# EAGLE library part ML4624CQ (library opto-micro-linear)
FIBER OPTIC DATA QUANTIZER
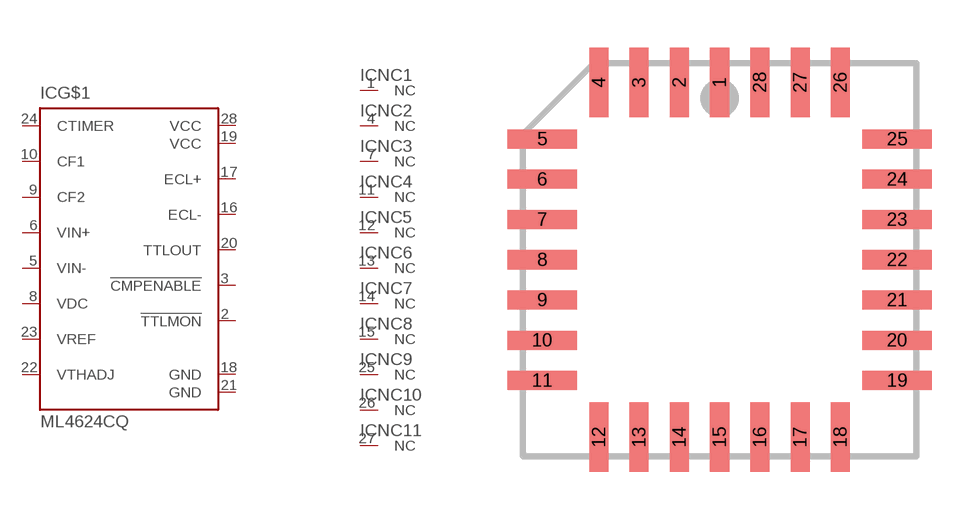
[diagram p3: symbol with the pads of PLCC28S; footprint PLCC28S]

Designator prefix IC; gates G$1=ML4624 NC1=NC NC2=NC NC3=NC NC4=NC NC5=NC NC6=NC NC7=NC NC8=NC NC9=NC NC10=NC NC11=NC

## ML4624CQ (OC_FARNELL: unknown; OC_NEWARK: unknown)  [PLCC28S]
1  NC1:NC  nc
2  G$1:!TTLMON  out
3  G$1:!CMPENABLE  in
4  NC2:NC  nc
5  G$1:VIN-  in
6  G$1:VIN+  in
7  NC3:NC  nc
8  G$1:VDC  pas
9  G$1:CF2  pas
10  G$1:CF1  pas
11  NC4:NC  nc
12  NC5:NC  nc
13  NC6:NC  nc
14  NC7:NC  nc
15  NC8:NC  nc
16  G$1:ECL-  out
17  G$1:ECL+  out
18  G$1:GND  pwr
19  G$1:VCC  pwr
20  G$1:TTLOUT  out
21  G$1:GND  pwr
22  G$1:VTHADJ  in
23  G$1:VREF  in
24  G$1:CTIMER  pas
25  NC9:NC  nc
26  NC10:NC  nc
27  NC11:NC  nc
28  G$1:VCC  pwr

## Footprint PLCC28S (pad centres in mm)
Plastic Leaded Chip Carrier square
smd 0.6 x 2.2: 1 0,5.6; 2 -1.27,5.6; 3 -2.54,5.6; 4 -3.81,5.6; 12 -3.81,-5.6; 13 -2.54,-5.6; 14 -1.27,-5.6; 15 0,-5.6; 16 1.27,-5.6; 17 2.54,-5.6; 18 3.81,-5.6; 26 3.81,5.6; 27 2.54,5.6; 28 1.27,5.6
smd 2.2 x 0.6: 5 -5.6,3.81; 6 -5.6,2.54; 7 -5.6,1.27; 8 -5.6,0; 9 -5.6,-1.27; 10 -5.6,-2.54; 11 -5.6,-3.81; 19 5.6,-3.81; 20 5.6,-2.54; 21 5.6,-1.27; 22 5.6,0; 23 5.6,1.27; 24 5.6,2.54; 25 5.6,3.81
